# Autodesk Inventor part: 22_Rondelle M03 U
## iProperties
Created: 2002-07
Part Number: 22_Rondelle M03 U
Material: X5 Cr Ni 18-10
Document SubType Name: Modélisation
Designer: FIEVET
Company: Lycée Joliot Curie
Control State: 0
Master: False
Checked Out: False
Shininess: 20.0
Length Units: 11269
Angle Units: 11279
Time Units: 11290
Mass Units: 11283
Length Display Precision: 3
Angle Display Precision: 2
Compacted: True
Density: 0.0
Volumn: 0.0
Area: 0.0
PropertySet Name: Model Information
Title: Rondelle plate
Subject: NF E 25-514
Author: FIEVET
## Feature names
1. Extrusion1
2. Chanfrein1 [Chamfer]
